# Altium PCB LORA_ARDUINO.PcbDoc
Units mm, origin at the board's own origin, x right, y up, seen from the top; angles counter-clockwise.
Board outline 68.58 x 53.34 mm, 2 copper layers (Top Layer, Bottom Layer); 51 components, 44 nets, 217 pads, 39 vias.
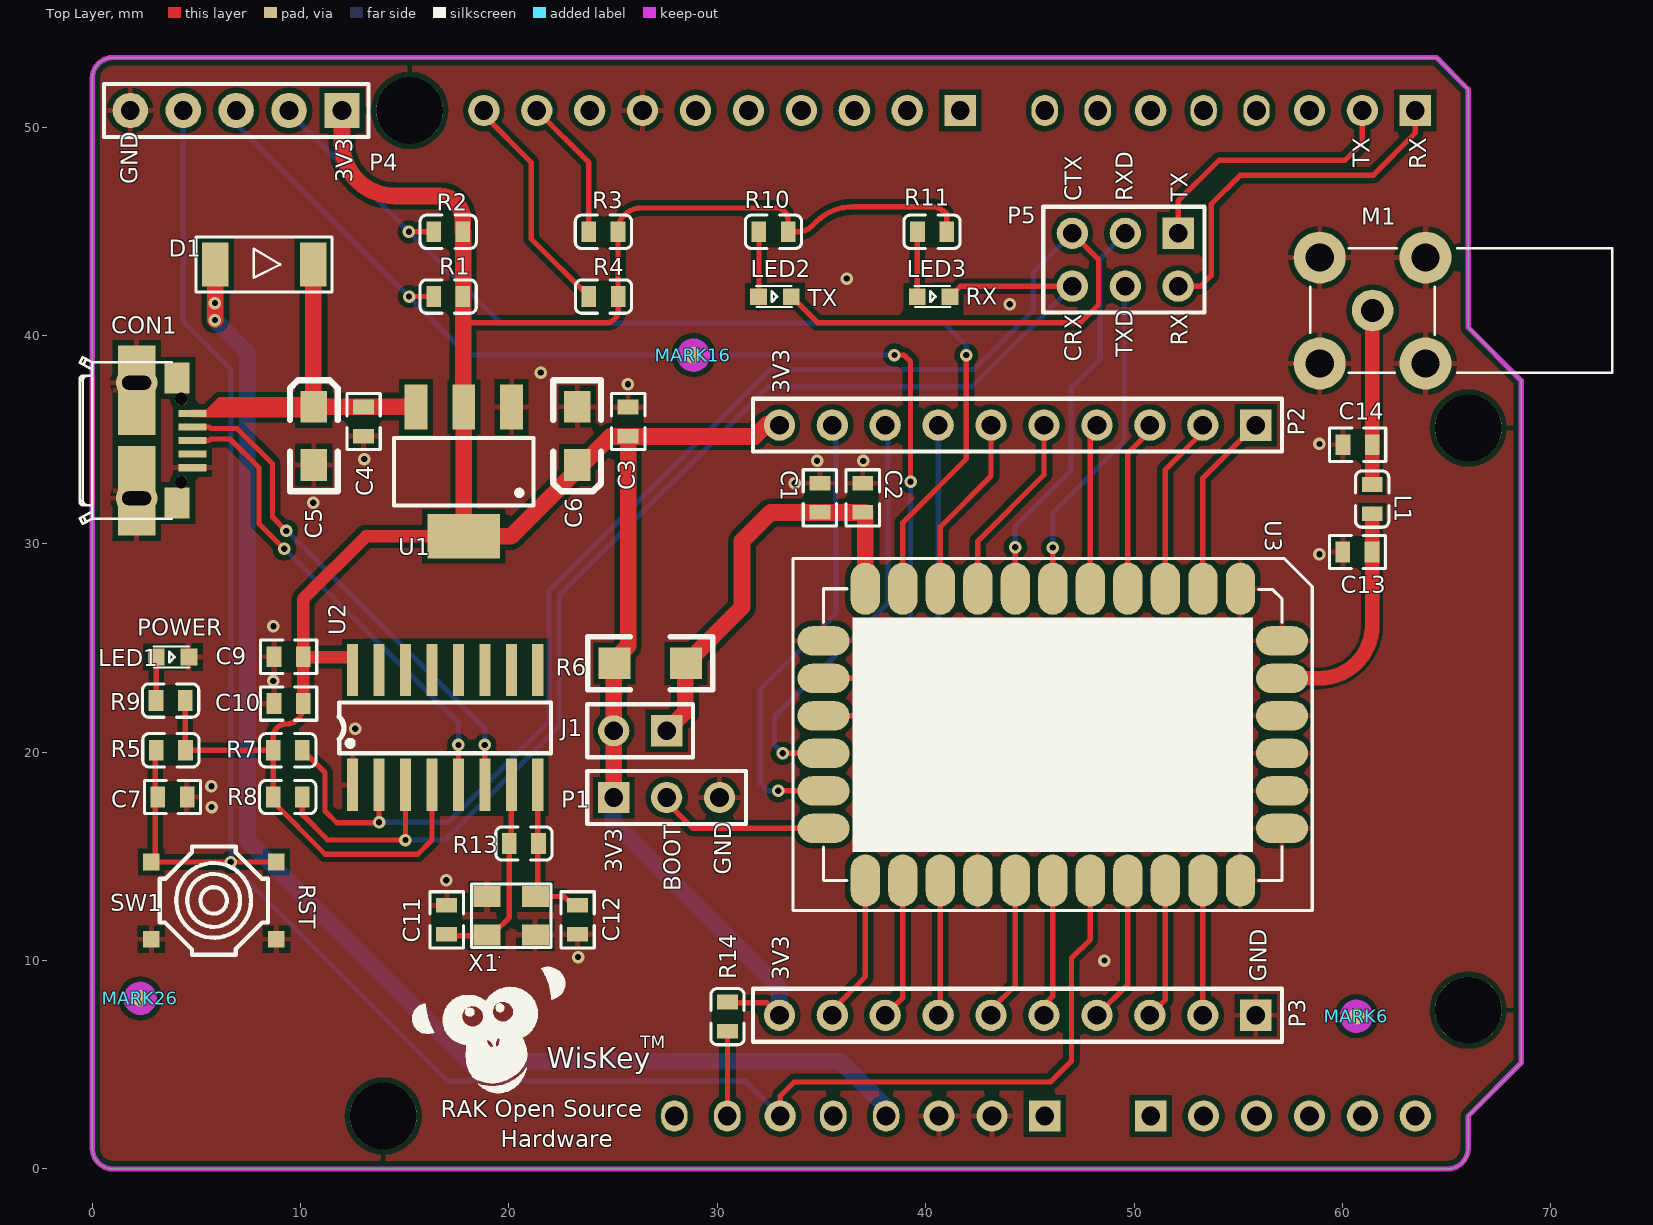
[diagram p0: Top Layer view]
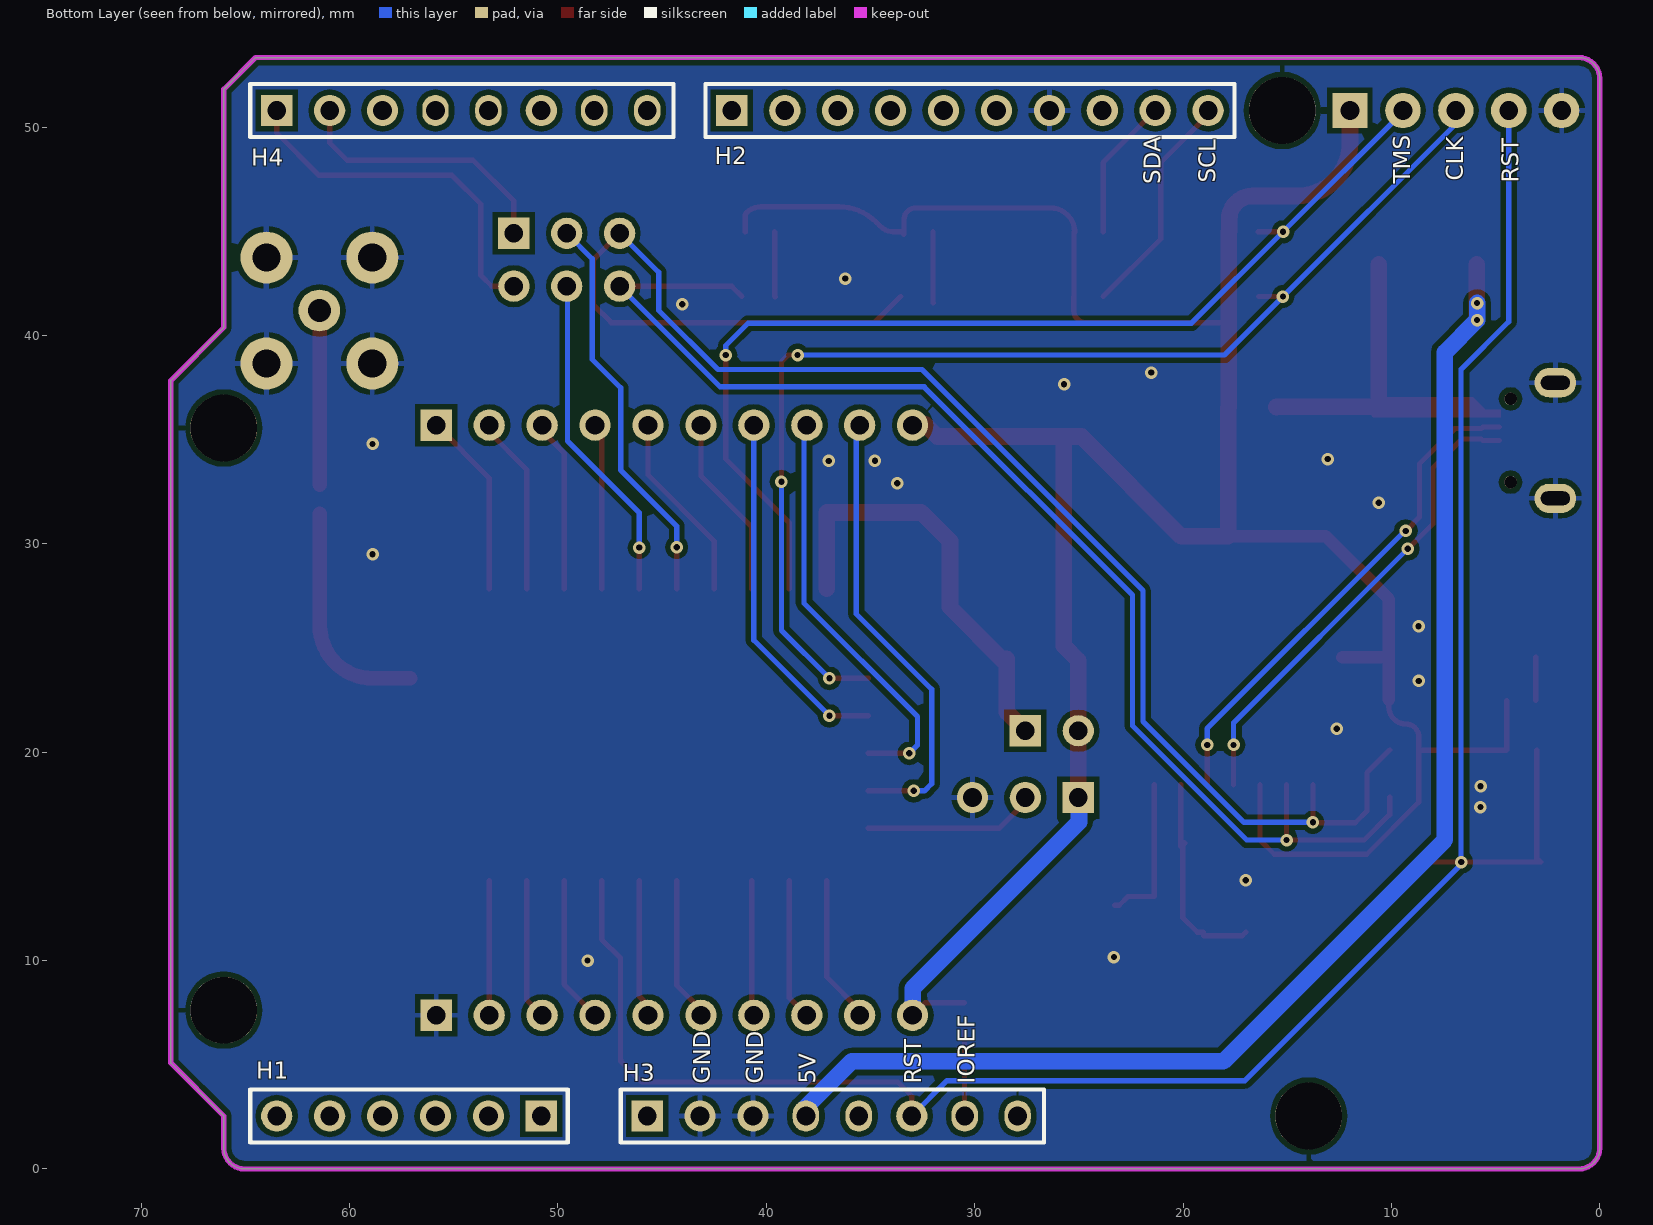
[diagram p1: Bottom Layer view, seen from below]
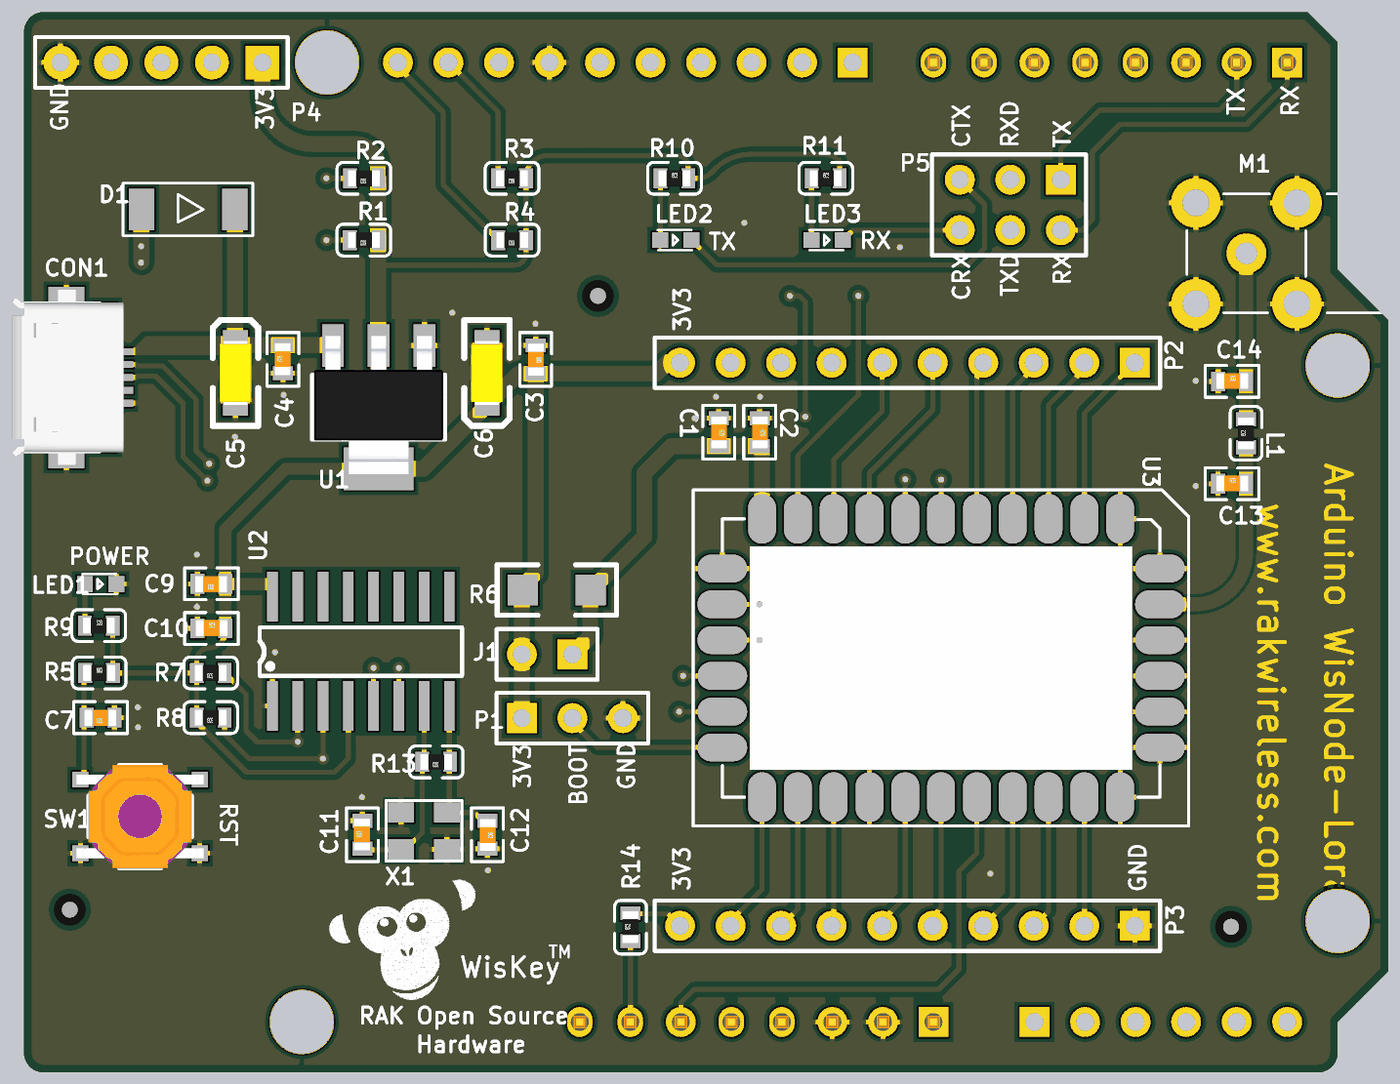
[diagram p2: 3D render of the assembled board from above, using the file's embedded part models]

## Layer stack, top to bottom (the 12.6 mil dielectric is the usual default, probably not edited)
Top Layer: signal copper 0.0356
Dielectric: dielectric 0.32, FR-4, Dk 4.8
Bottom Layer: signal copper 0.0356

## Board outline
0,1 0,52.34 cw(c1,52.34) 1,53.34 64.516,53.34 66.04,51.816 66.04,40.386 68.58,37.846 68.58,5.08 66.04,2.54 66.04,1 cw(c65.04,1) 65.04,0 1,0 cw(c1,1)

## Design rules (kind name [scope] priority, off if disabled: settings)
Clearance Clearance_1 [All vs InNet('RF_1','RF_OUT') And OnLayer('Top Layer')] p1: gap=0.152
Clearance [All] p2: gap=0.254
MinimumSolderMaskSliver MinimumSolderMaskSliver_1 [All] p1: minsoldermaskwidth=0
MinimumSolderMaskSliver [All] p2: minsoldermaskwidth=0.254
PolygonConnect PolygonConnect_1 [IsVia] p1: connectstyle=Direct reliefconductorwidth=0.254 reliefentries=4 polygonreliefangle="90 Angle"
PolygonConnect [All] p2: connectstyle=Relief reliefconductorwidth=0.254 reliefentries=4 polygonreliefangle="90 Angle"
RoutingVias [All] p1: holewidth=0.711 width=1.27 viastyle="Through Hole" minholewidth=0.711 minwidth=1.27 maxholewidth=0.711 maxwidth=1.27
SilkToSilkClearance SilkToSilkClearance_1 [All] p1: silktosilkclearance=0
SilkToSilkClearance [All] p2: silktosilkclearance=0.254
SilkscreenOverComponentPads SilkscreenOverComponentPads_1 [All] p1: minsilkscreentomaskgap=0
SilkscreenOverComponentPads [All] p2: minsilkscreentomaskgap=0.254
SolderMaskExpansion [All] p1: expansion=0.102
Width [All] p1: maxlimit=1 minlimit=0.254 preferedwidth=0.254
25 further rules are at their usual default settings.

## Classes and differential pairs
component class LORA_ARDUINO: C1 C2 C3 C4 C5 C6 C7 C9 C10 C11 C12 C13 C14 CON1 D1 H1 H2 H3 H4 J1 L1 LED1 LED2 LED3 M1 P1 P2 P3 P4 P5 R1 R2 R3 R4 R5 R6 R7 R8 R9 R10 R11 R13 R14 SW1 U1 U2 U3 X1
net class RF: RF_1 RF_OUT

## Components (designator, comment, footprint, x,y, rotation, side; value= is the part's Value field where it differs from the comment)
C1 "Cap" 0603AC 34.923,32.208 r270 top
C2 "Cap" 0603AC 36.98,32.208 r270 top
C3 "0.1μF" 0603AC 25.722,35.871 r270 top
C4 "0.1μF" 0603AC 13.022,35.871 r90 top
C5 "22uF" 3216 10.634,35.185 r90 top
C6 "22uF" 3216 23.275,35.185 r270 top
C7 "0.1uF" 0603AC 3.851,17.851 r180 top
C9 "10uF" 0603AC 9.423,24.58 r180 top
C10 "0.1uF" 0603AC 9.423,22.337 r0 top
C11 "20pF" 0603AC 17.01,11.955 r90 top
C12 "20pF" 0603AC 23.295,11.955 r270 top
C13 "0.1μF" 0603AC 60.725,29.609 r0 top
C14 "0.1μF" 0603AC 60.73,34.758 r0 top
CON1 "MICRO USB" "Micro USB通用" 3.47,34.961 r90 top
D1 "SS24A" SMA/DO-214A 8.255,43.409 r0 top
H1 "" HDR1X6 50.8,2.54 r0 bottom locked
H2 "" HDR1X10 41.656,50.8 r180 bottom locked
H3 "" HDR1X8 45.72,2.54 r180 bottom locked
H4 "" HDR1X8 63.5,50.8 r180 bottom locked
J1 "" HDR1X2 27.569,21.031 r180 top
L1 "" 0603AR 61.431,32.149 r90 top
LED1 "" LED0603 3.068,24.567 r0 top
LED2 "" LED0603 31.981,41.868 r0 top
LED3 "" LED0603 39.59,41.868 r0 top
M1 "MCX-KWE" SMA-KWE天线底座 58.912,43.741 r180 top
MARK6 "" MARK_0.8 60.678,7.329 r90 top
MARK16 "" MARK_0.8 28.856,39.06 r90 top (schematic designator MARK6)
MARK26 "" MARK_0.8 2.305,8.185 r90 top (schematic designator MARK6)
P1 "" HDR1X3 25.029,17.823 r0 top
P2 "" HDR1X10 55.84,35.697 r180 top
P3 "" HDR1X10 55.84,7.376 r180 top
P4 "" HDR1X5 11.989,50.8 r180 top
P5 "" HDR2X3 46.787,43.764 r180 top
R1 "10K" 0603AR 17.083,41.868 r180 top
R2 "10K" 0603AR 17.086,44.979 r180 top
R3 "" 0603AR 24.535,44.979 r180 top
R4 "Res1" 0603AR 24.54,41.868 r180 top
R5 "10K/5%" 0603AR 3.777,20.094 r0 top
R6 "0R/1%" 1206 26.783,24.266 r0 top
R7 "10K" 0603AR 9.385,20.094 r180 top
R8 "10K" 0603AR 9.385,17.851 r180 top
R9 "1K/5%" 0603AR 3.762,22.481 r0 top
R10 "1K/5%" 0603AR 32.698,44.979 r0 top
R11 "1K/5%" 0603AR 40.307,44.979 r0 top
R13 "1M" 0603AR 20.718,15.619 r180 top
R14 "Res1" 0603AR 30.49,7.31 r90 top
SW1 "KEY3" YH/4脚SMD轻触开关_3D_2 5.838,12.878 r270 top
U1 "LM1117IMPX-3.3" SOT-223 17.831,33.463 r180 top
U2 "CH340G" "SOIC16 - խ" 16.94,21.189 r0 top
U3 "LORA Model" LORA 55.104,27.848 r270 top locked
X1 "12MHz" XTAL-3.2X2.5 20.108,12.153 r0 top

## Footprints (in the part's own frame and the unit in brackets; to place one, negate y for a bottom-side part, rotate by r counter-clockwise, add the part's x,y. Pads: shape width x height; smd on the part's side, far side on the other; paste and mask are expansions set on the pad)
0603AC [mm]
  rect 0.7x1 smd: 1(-0.7,0) 2(0.7,0)
  silkscreen extent -1.35,-0.8 1.35,0.8, body extent -0.79,-0.38 0.81,0.42, height 0.3
0603AR [mm]
  rect 0.7x1 smd: 1(-0.7,0) 2(0.7,0)
  silkscreen extent -1.35,-0.8 1.35,0.8, body extent -0.8,-0.4 0.8,0.4, height 0.3
1206 [mil]
  rect 60x60 smd: 1(-67.5,0) 2(67.5,0)
  silkscreen extent -118,-50 118,50
3216 [mil]
  rect 60x50 smd: 1(55,0) 2(-55,0)
  silkscreen extent -105,-45 105,45, body extent -63,-31 63,31, height 63
HDR1X2 [mm] "Connector; Header; 2 Posit"
  rect 1.5x1.5 hole 0.9: 1(0,0)
  round 1.5 hole 0.9: 2(2.54,0)
  silkscreen extent -1.27,-1.27 3.81,1.27
HDR1X3 [mm] "Connector; Header; 3 Posit"
  rect 1.5x1.5 hole 0.9: 1(0,0)
  round 1.5 hole 0.9: 2(2.54,0) 3(5.08,0)
  silkscreen extent -1.27,-1.27 6.35,1.27
HDR1X5 [mm] "Connector; Header; 5 Position"
  rect 1.7x1.7 hole 0.9: 1(0,0)
  round 1.7 hole 0.9: 2(2.54,0) 3(5.08,0) 4(7.62,0) 5(10.16,0)
  silkscreen extent -1.27,-1.27 11.43,1.27
HDR1X6 [mm]
  rect 1.5x1.5 hole 0.9: 1(0,0)
  round 1.5 hole 0.9: 2(2.54,0) 3(5.08,0) 4(7.62,0) 5(10.16,0) 6(12.7,0)
  silkscreen extent -1.27,-1.27 13.97,1.27
HDR1X8 [mm] "Connector; Header; 8 Position"
  rect 1.5x1.5 hole 0.9: 1(0,0)
  round 1.5 hole 0.9: 2(2.54,0) 3(5.08,0) 6(12.7,0)
  oval 1.27x1.5 hole 0.9: 4(7.62,0) 5(10.16,0) 7(15.24,0) 8(17.78,0)
  silkscreen extent -1.27,-1.27 19.05,1.27, body extent -1.27,-1.27 19.05,1.27, height 0.7
HDR1X10 [mm] "Connector; Header; 10 Posit"
  rect 1.5x1.5 hole 0.9: 1(0,0)
  round 1.5 hole 0.9: 2(2.54,0) 3(5.08,0) 4(7.62,0) 5(10.16,0) 6(12.7,0) 7(15.24,0) 8(17.78,0) 9(20.32,0) 10(22.86,0)
  silkscreen extent -1.27,-1.27 24.13,1.27
HDR2X3 [mm]
  rect 1.5x1.5 hole 0.9: 1(-5.334,-1.143)
  round 1.5 hole 0.9: 2(-5.334,1.397) 3(-2.794,-1.143) 4(-2.794,1.397) 5(-0.254,-1.143) 6(-0.254,1.397)
  silkscreen extent -6.6,-2.41 1.14,2.67
LED0603 [mm]
  rect 0.8x0.8 smd: 1(0,0) 2(1.575,0)
  silkscreen extent -0.13,-0.51 1.6,0.51, body extent -0.06,-0.47 1.64,0.48, height 0.9
LORA [mm]
  oval 2.5x1.4 smd: 1(0,0) 2(0,-1.8) 3(0,-3.6) 4(0,-5.4) 5(0,-7.2) 6(0,-9) 7(0,-10.8) 8(0,-12.6) 9(0,-14.4) 10(0,-16.2) 11(0,-18) 18(14,-18) 19(14,-16.2) 20(14,-14.4) 21(14,-12.6) 22(14,-10.8) 23(14,-9) 24(14,-7.2) 25(14,-5.4) 26(14,-3.6) 27(14,-1.8) 28(14,0)
  oval 1.4x2.5 smd: 12(2.5,-20) 13(4.3,-20) 14(6.1,-20) 15(7.9,-20) 16(9.7,-20) 17(11.5,-20) 29(11.5,2) 30(9.7,2) 31(7.9,2) 32(6.1,2) 33(4.3,2) 34(2.5,2)
  silkscreen extent -1.45,-21.46 15.45,3.45
MARK_0.8 [mm]
  round 0.8 smd: 1(0,0)
  Top Layer keep-out circle w0.4: c0,0 r0.6
"Micro USB通用" [mm]
  rect 0.35x1.349 smd: 1(1.3,-1.34) 2(0.65,-1.34) 3(0,-1.34) 4(-0.65,-1.34) 5(-1.3,-1.34)
  rect 4.3x1.8 smd: 6(2.413,1.34) 7(-2.413,1.34)
  oval 1.4x2 hole 0.66 slot 1.4 at 90 deg: 6(2.775,1.34) 7(-2.775,1.34)
  rect 1.5x1.2 smd: 8(3,-0.61) 9(-3,-0.61)
  round 0.6 hole 0.6 unplated paste+0: ""(-2,-0.81) ""(2,-0.81)
  silkscreen extent -4.03,-0.35 4.03,4.08, body extent -4.4,-1.53 4.4,4.07, height 2.74
SMA-KWE天线底座 [mm]
  round 2 hole 1.1: 1(-2.54,2.54)
  round 2.5 hole 1.35: 2(-5.08,5.08) 3(-5.08,0) 4(0,0) 5(0,5.08)
  silkscreen extent -14.05,-0.45 0.45,5.53
SMA/DO-214A [mm]
  rect 1.27x2.1 smd: 1(-2.349,0) 2(2.349,0)
  silkscreen extent -3.28,-1.32 3.25,1.32
"SOIC16 - խ" [mm]
  rect 0.533x2.5 smd: 1(-4.445,-2.75) 2(-3.175,-2.75) 3(-1.905,-2.75) 4(-0.635,-2.75) 5(0.635,-2.75) 6(1.905,-2.75) 7(3.175,-2.75) 8(4.445,-2.75) 9(4.445,2.75) 10(3.175,2.75) 11(1.905,2.75) 12(0.635,2.75) 13(-0.635,2.75) 14(-1.905,2.75) 15(-3.175,2.75) 16(-4.445,2.75)
  silkscreen extent -5.08,-1.24 5.08,1.2
SOT-223 [mm] "SOT-223/SC-73; 4 Leads; Body 6.7 x 7.3 mm, inc. leads (LxW max)"
  rect 1.1x2.15 smd: 1(2.3,-3.1) 2(0,-3.1) 3(-2.3,-3.1)
  rect 3.5x2.15 smd: 2(0,3.1)
  silkscreen extent -3.35,-1.63 3.35,1.63, body extent -3.25,-3.58 3.25,3.38, height 1.65
XTAL-3.2X2.5 [mil] "XTAL-3.2X2.5"
  rect 51x40 smd: 1(-45.5,-36.5) 2(45.5,-36.5) 3(45.5,36.5) 4(-45.5,36.5)
  silkscreen extent -75,-60 75,60
YH/4脚SMD轻触开关_3D_2 [mm] "4脚 按键 4X4X1.5贴片铜头防水"
  rect 0.8x0.8 smd: 1(1.85,3) 2(1.85,-3) 3(-1.85,3) 4(-1.85,-3)
  silkscreen extent -2.6,-2.6 2.6,2.6, body extent -2.6,-3.2 2.6,3.2, height 1.5

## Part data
C1 C2: "Capacitor"
C3: library part Cap, "Capacitor"
C4 C9 C10 C13 C14: library part CAP, "Capacitor"
C5 C6: library part CAP
C7: library part C
C11 C12: library part "CAP NP_Dup1"
D1: library part DIODE
H1: library part "Header 6", "Header, 6-Pin"
H2 P2 P3: library part "Header 10", "Header, 10-Pin"
H3 H4: library part "Header 8", "Header, 8-Pin"
J1: library part "Header 2", "Header, 2-Pin"
L1 R5 R7 R8: library part RES
LED1 LED2 LED3: library part LED
MARK6 MARK16 MARK26: library part MARK点
P1: library part "Header 3", "Header, 3-Pin"
P4: library part "Header 5", "Header, 5-Pin"
P5: library part "Header 3X2", "Header, 3-Pin, Dual row"
R1 R2: library part R_5
R3: library part Res1, "Resistor"
R4 R14: "Resistor"
R6 R9 R10 R11: library part Res2, "Resistor"
R13: library part R_0
SW1: library part KEY1
U1: "Voltage Regulator"
U2: "USB to TTL Serial / UART"
X1: library part Crystal_SMD_2

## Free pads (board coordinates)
  round 3.2 hole 3.2: 1(13.97,2.54) 1(15.24,50.8) 1(66.04,7.62) 1(66.04,35.56)

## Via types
v1: diameter 0.6, hole 0.3, Top Layer to Bottom Layer, tented both sides, 39 vias

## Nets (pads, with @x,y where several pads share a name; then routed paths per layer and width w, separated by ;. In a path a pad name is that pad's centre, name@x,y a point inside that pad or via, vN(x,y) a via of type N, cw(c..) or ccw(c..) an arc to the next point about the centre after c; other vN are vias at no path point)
A_RX: H4.1 P5.2 | length 17.5
  Top Layer w0.254: P5.2 53.181,42.367 53.703,42.889 53.703,46.301 55.089,47.686 61.468,47.686 63.5,49.719 H4.1
A_TX: H4.2 P5.1 | length 13.1
  Top Layer w0.254: P5.1 52.121,46.453 54.078,48.41 60.118,48.41 60.96,49.252 H4.2
BOOT0: P1.2 U3.17 | length 8.2
  Top Layer w0.254: P1.2@27.691,17.823 27.691,17.494 28.837,16.348 U3.17
CH_RX: LED3.2 P5.6 R8.1 U2.3 | length 61.7
  Top Layer w0.254: R8.1 10.085,17.006 11.305,15.786 v1(15.035,15.786) U2.3 ; LED3.2 41.664,42.367 P5.6
  Bottom Layer w0.254: v1(15.035,15.786) 16.944,15.786 22.43,21.272 22.43,27.542 32.426,37.538 42.211,37.538 P5.6
CH_TX: LED2.2 P5.5 R7.1 U2.2 | length 77.3
  Top Layer w0.254: R7.1@10.085,20.107 11.17,19.022 11.17,17.181 11.734,16.617 13.765,16.617 v1(13.765,16.635) U2.2 ; LED2.2 34.806,40.619 47.438,40.619 48.292,41.473 48.292,43.656 P5.5
  Bottom Layer w0.254: v1(13.765,16.635) 17.075,16.635 21.922,21.482 21.922,27.756 32.531,38.365 42.32,38.365 45.168,41.213 45.168,43.035 P5.5
CHRG: P2.1 U3.2 | length 8.9
  Top Layer w0.254: U3.2 53.304,33.16 P2.1
GND: C1.1 C2.1 C3.1 C4.1 C5.2 C6.2 C7.1 C9.2 C10.1 C11.2 C12.2 C13.1 C14.1 CON1.5 CON1.6 CON1.7 H2.7 H3.2 H3.3 LED1.2 M1.2 M1.3 M1.4 M1.5 P1.3 P3.1 P4.5 SW1.1 SW1.2 U1.3 U2.1 U3.1 U3.12 U3.21 U3.28 U3.29 U3.30 U3.31 U3.32 U3.34 X1.2 X1.4
  other v1: 48.578,10.004 23.316,10.168 16.99,13.85 5.729,17.367 5.724,18.365 12.622,21.132 8.694,23.423 8.695,26.049 58.901,29.5 10.612,31.974 33.712,32.909 34.79,33.986 37.002,33.979 13.053,34.073 58.901,34.794 25.713,37.655 21.526,38.22 44.039,41.504 36.209,42.736
INT_ACC1: P2.3 U3.4 | length 8.3
  Top Layer w0.254: U3.4 49.704,34.362 50.76,35.419 P2.3
INT_ACC2: P2.2 U3.3 | length 8.6
  Top Layer w0.254: U3.3 51.504,33.574 53.3,35.371 P2.2
LVCC_3V3: C1.2 C2.2 J1.1 R6.2 U3.11 | length 21
  Top Layer w0.8: J1.1 28.461,21.923 R6.2@28.461,24.477 ; R6.2 31.189,26.958 31.189,30.138 32.56,31.508 C2.2@37.107,31.508 ; C2.2 37.104,31.385 U3.11 U3.11@37.107,27.851
NetD1_1: D1.1 H3.4 | length 65.5
  Top Layer w0.8: v1@5.905,40.761 D1.1
  Bottom Layer w0.8: v1(5.886,41.561) v1(5.886,40.742) 7.437,39.192 7.437,15.792 18.064,5.164 35.905,5.164 38.1,2.97 H3.4
NetH2_9: H2.9 R3.2 | length 6.9
  Top Layer w0.254: H2.9 23.835,48.301 R3.2
NetH2_10: H2.10 R4.2 | length 11
  Top Layer w0.254: H2.10 18.796,50.58 21.072,48.305 21.072,44.636 R4.2
NetH3_7: H3.7 R14.1 | length 4.1
  Top Layer w0.254: H3.7 30.49,2.54 R14.1
NetLED1_1: LED1.1 R9.1 | length 2.1
  Top Layer w0.254: R9.1 ccw(c3.062,22.487) 3.068,22.487 LED1.1
NetLED2_1: LED2.1 R10.1 | length 3.4
  Top Layer w0.254: LED2.1@31.981,41.562 31.998,41.579 R10.1
NetLED3_1: LED3.1 R11.1 | length 3.2
  Top Layer w0.254: LED3.1@39.58,41.857 LED3.1 R11.1@39.59,44.939 ; R11.1@39.59,44.939 cw(c39.647,44.939) R11.1 ccw(c39.647,44.939) R11.1@39.59,44.939
PA15: P2.7 U3.14 | length 17.3
  Top Layer w0.254: U3.14 v1(36.974,21.748)
  Bottom Layer w0.254: v1(36.974,21.748) 40.6,25.374 P2.7
PB10: P3.4 U3.25 | length 7.1
  Top Layer w0.254: P3.4 49.704,8.859 U3.25
RF_1: C14.2 L1.2 M1.1 | length 8.4
  Top Layer w0.709: M1.1@61.423,41.172 cw(c61.452,41.172) M1.1 ccw(c61.452,41.179) 61.431,41.179 L1.2
RF_OUT: C13.2 L1.1 U3.33 | length 11.1
  Top Layer w0.709: U3.33 58.891,23.548 ccw(c58.891,26.088) 61.431,26.088 L1.1
RST: C7.2 H3.6 P4.4 R5.1 SW1.3 SW1.4 U3.24 | length 105
  Top Layer w0.254: R5.1@3.021,20.094 3.021,14.911 SW1.4 SW1.3 ; P4.4@4.369,50.416 P4.4 ; H3.6 33.02,3.5 33.696,4.176 45.984,4.176 46.993,5.184 ; 46.993,5.215 47.004,5.226 47.004,10.121 47.904,11.02 U3.24
  Bottom Layer w0.254: P4.4 4.369,40.665 6.656,38.378 v1@6.656,14.728 ; v1@6.667,14.728 6.667,14.604 17.036,4.235 31.325,4.235 H3.6
  other v1: 6.651,14.728
SCL: P3.3 U3.26 | length 6.8
  Top Layer w0.254: P3.3 51.504,8.119 U3.26
SCL1: P3.9 U3.18 | length 7.1
  Top Layer w0.254: P3.9 35.52,7.624 37.104,9.207 U3.18
SDA: P3.2 U3.27 | length 6.5
  Top Layer w0.254: P3.2 53.304,7.379 U3.27
SDA1: P3.8 U3.19 | length 6.8
  Top Layer w0.254: P3.8 38.904,8.219 U3.19
SW_PB_SPST1: P2.8 U3.15 | length 20
  Top Layer w0.254: v1(33.138,19.948) U3.15
  Bottom Layer w0.254: v1(33.138,19.948) 32.747,20.339 32.747,21.706 38.189,27.148 P2.8@38.189,35.568
SW_PB_SPST2: P2.9 U3.16 | length 21.7
  Top Layer w0.254: v1(32.929,18.148) U3.16
  Bottom Layer w0.254: v1(32.929,18.148) 32.406,18.148 32.067,18.487 32.067,23.025 35.691,26.648 P2.9@35.691,35.526
SWD_CLK: P4.3 R1.2 U3.13 | length 57.1
  Top Layer w0.254: 15.521,41.868 R1.2 ; U3.13 v1(36.974,23.548) ; v1(38.505,39.06) 38.963,39.06 39.278,38.745 v1(39.278,32.987)
  Bottom Layer w0.254: P4.3@6.909,50.296 P4.3 6.909,50.167 v1(15.207,41.868) 18.015,39.06 v1(38.505,39.06) ; v1(36.974,23.548) 39.278,25.852 v1(39.278,32.987)
SWD_TMS: P4.2 R2.2 U3.10 | length 51.7
  Top Layer w0.254: v1(15.198,44.979) R2.2 ; U3.10 38.904,31.027 41.946,34.07 v1(41.946,39.063)
  Bottom Layer w0.254: P4.2@9.449,50.374 P4.2@9.449,50.728 ; P4.2 P4.2@9.449,50.728 ; v1(15.198,44.979) P4.2@9.449,50.728 ; v1@15.212,44.979 19.596,40.595 40.869,40.595 41.946,39.518 v1(41.946,39.063)
SYNC: P2.4 U3.5 | length 8
  Top Layer w0.254: U3.5 47.904,35.38 P2.4
UART1_CTS: P2.6 U3.9 | length 8.9
  Top Layer w0.254: U3.9 40.704,30.823 43.14,33.26 P2.6
UART1_RTS: P2.5 U3.8 | length 9.2
  Top Layer w0.254: U3.8 42.504,30.142 45.68,33.318 P2.5
UART1_RX: P5.3 U3.7 | length 19.2
  Top Layer w0.254: U3.7 v1(44.304,29.836)
  Bottom Layer w0.254: v1(44.304,29.836) 44.304,30.858 46.995,33.549 46.995,37.492 48.354,38.852 48.354,43.681 P5.3
UART1_TX: P5.4 U3.6 | length 15.9
  Top Layer w0.254: U3.6 v1(46.104,29.821)
  Bottom Layer w0.254: v1(46.104,29.821) 46.104,31.497 49.547,34.941 P5.4@49.547,42.367
UART4_RX: P3.6 U3.22 | length 7
  Top Layer w0.254: P3.6 43.14,7.651 44.304,8.815 U3.22
UART4_TX: P3.5 U3.23 | length 6.6
  Top Layer w0.254: P3.5 45.68,7.867 46.104,8.291 U3.23
USB_DM: CON1.2 U2.6 | length 24.2
  Top Layer w0.254: CON1.2 5.611,35.611 5.682,35.54 6.955,35.54 8.647,33.848 8.647,31.284 v1(9.309,30.623) ; U2.6 v1(18.845,20.35)
  Bottom Layer w0.254: v1@9.333,30.648 18.845,21.137 v1(18.845,20.35)
USB_DP: CON1.3 U2.5 | length 22.6
  Top Layer w0.254: CON1.3 5.611,34.961 ; 5.682,35.032 6.621,35.032 8.001,33.651 8.001,30.966 v1@9.047,29.92 ; U2.5 v1(17.575,20.348)
  Bottom Layer w0.254: v1(9.218,29.767) 17.575,21.411 v1(17.575,20.348)
VBAT_ANA: P3.7 U3.20 | length 6.5
  Top Layer w0.254: P3.7 40.704,7.479 U3.20
VCC5V: C4.2 C5.1 CON1.1 D1.2 U1.1 | length 11.5
  Top Layer w0.8: D1.2 10.61,43.403 C5.1@10.61,36.785 ; C5.1 15.512,36.582 U1.1
VCC_3V3: C3.2 C6.1 C9.1 C10.2 J1.2 P1.1 P2.10 P3.10 P4.1 R1.1 R2.1 R3.1 R4.1 R5.2 R6.1 R7.2 R8.2 R9.2 R10.2 R11.2 R14.2 U1.2 U2.4 U2.16 | length 147.7
  Top Layer w0.254: R9.2 4.462,20.109 R5.2 R7.2 ; C10.2@10.123,22.512 10.123,22.178 cw(c9.296,22.178) 9.296,21.351 ccw(c9.296,20.74) 8.685,20.74 R7.2 ; P4.1@11.419,50.23 P4.1 ; U2.4 16.305,15.788 15.621,15.105 11.183,15.105 8.685,17.602 R8.2 R7.2 ; 17.807,40.645 ccw(c17.843,40.645) 17.843,40.609 24.656,40.609 ccw(c24.656,41.192) 25.24,41.192 R4.1 25.235,41.873 R3.1 ; R3.1@25.182,45.048 25.182,44.987 ccw(c25.202,44.987) 25.202,44.967 cw(c26.36,44.967) 26.36,46.125 32.82,46.125 cw(c32.82,45.556) 33.389,45.556 33.389,44.865 ccw(c33.389,44.874) 33.398,44.874 R10.2 ; R14.2@30.49,7.977 32.379,7.977 P3.10 ; R10.2@33.443,44.869 cw(c33.552,44.979) R10.2 ; R11.2@41.007,44.967 cw(c41.004,44.965) R11.2@41.008,44.965 ; R11.2 41.007,45.781 ccw(c40.859,45.781) 40.964,45.886 ccw(c40.242,45.164) 40.242,46.185 36.523,46.185 ccw(c36.523,43.645) 34.727,45.441 34.518,45.232 cw(c33.906,45.844) 33.906,44.979 R10.2
  Top Layer w0.6: C10.2@10.123,22.512 C9.1 10.123,27.346 13.141,30.363 U1.2@17.831,30.363 ; C9.1@10.212,24.561 U2.16@12.351,24.561
  Top Layer w0.8: P4.1 11.989,49.238 ccw(c14.529,49.238) 14.529,46.698 16.671,46.698 cw(c16.671,45.583) 17.786,45.583 R2.1 ; U1.2@17.807,36.563 R2.1@17.807,44.979 ; U1.2@17.831,36.563 17.831,30.363 20.089,30.363 24.875,35.15 31.797,35.15 32.388,35.741 P2.10@32.98,35.741 ; P1.1 25.029,20.889 25.029,24.407 25.722,25.1 C3.2@25.722,35.059 ; J1.2@25.032,21.239 J1.2@25.045,21.226
  Bottom Layer w0.8: P1.1@25.16,17.993 24.994,17.826 24.994,16.654 32.98,8.667 P3.10
XIN: C11.1 R13.2 U2.7 X1.1 | length 10.2
  Top Layer w0.254: C11.1@16.997,11.358 17.158,11.198 X1.1@19,11.198 ; X1.1@19.016,11.36 19.315,11.36 20.018,12.062 R13.2 ; R13.2@19.991,15.692 19.926,15.627 R13.2@20.092,15.46 ; R13.2@20.115,15.513 U2.7
XOUT: C12.1 R13.1 U2.8 X1.3 | length 7.4
  Top Layer w0.254: U2.8 21.385,13.08 22.637,13.08 23.062,12.655 C12.1
pads on no net: CON1. CON1.4 CON1.8 CON1.9 H1.1 H1.2 H1.3 H1.4 H1.5 H1.6 H2.1 H2.2 H2.3 H2.4 H2.5 H2.6 H2.8 H3.1 H3.5 H3.8 H4.3 H4.4 H4.5 H4.6 H4.7 H4.8 MARK6.1 MARK16.1 MARK26.1 U2.9 U2.10 U2.11 U2.12 U2.13 U2.14 U2.15

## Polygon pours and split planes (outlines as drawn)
GND on Top Layer "Top Layer-No Net" (solid, remove dead copper, pour order 1000): -0.227,53.494 -0.227,-0.493 -0.024,-0.696 69.161,-0.696 68.857,-0.392 68.857,53.7
GND on Bottom Layer "Top Layer-No Net" (solid, remove dead copper, pour order 1001): -0.17,53.549 -0.17,-0.416 -0.097,-0.49 -0.023,-0.564 69.52,-0.564 69.52,53.402 69.667,53.549

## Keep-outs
Keep-Out Layer:
  the board outline again, w0.254

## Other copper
Top Layer:
  region net VCC5V: 4.748,36.435 4.748,36.086 10.895,36.086 10.935,36.126 10.935,37.029 6.075,37.029 5.481,36.435

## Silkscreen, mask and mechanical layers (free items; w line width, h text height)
Top Overlay:
  drawing of 2317 lines, arcs and shapes, not listed
  text "TX" at 61.307,48.075 h0.8 r90
  text "RX" at 64.028,47.991 h0.8 r90
  text "3V3" at 12.504,47.335 h0.8 r90
  text "GND" at 2.176,47.251 h0.8 r90
  text "CTX" at 47.503,46.432 h0.8 r90
  text "RXD" at 49.936,46.432 h0.8 r90
  text "TX" at 52.569,46.427 h0.8 r90
  text "RX" at 41.928,41.472 h0.8
  text "TX" at 34.338,41.414 h0.8
  text "RX" at 52.569,39.516 h0.8 r90
  text "TXD" at 49.936,38.955 h0.8 r90
  text "CRX" at 47.503,38.739 h0.8 r90
  text "3V3" at 33.47,37.196 h0.8 r90
  text "POWER" at 2.165,25.581 h0.8
  text "3V3" at 25.442,14.214 h0.8 r90
  text "GND" at 30.67,14.13 h0.8 r90
  text "RST" at 9.902,13.667 h0.8 r270
  text "BOOT" at 28.241,13.334 h0.8 r90
  text "3V3" at 33.454,9.059 h0.8 r90
  text "GND" at 56.372,8.995 h0.8 r90
  text "TM" at 26.307,5.782 h0.6
  text "WisKey" at 21.814,4.821 h1
  text "RAK Open Source" at 16.736,2.48 h0.8
  text "Hardware" at 19.614,1.035 h0.8
Bottom Overlay:
  text "CLK" at 6.562,47.419 h0.8 r270
  text "RST" at 3.893,47.335 h0.8 r270
  text "SCL" at 18.421,47.327 h0.8 r270
  text "TMS" at 9.084,47.293 h0.8 r270
  text "SDA" at 21.072,47.259 h0.8 r270
  text "IOREF" at 29.996,4.078 h0.8 r270
  text "RST" at 32.559,4.078 h0.8 r270
  text "5V" at 37.64,4.078 h0.8 r270
  text "GND" at 40.159,4.078 h0.8 r270
  text "GND" at 42.688,4.078 h0.8 r270
Top Solder:
  text "Arduino WisNode-Lora" at 65.445,30.784 h1.3 r270
  text "www.rakwireless.com" at 63.117,29.236 h1.3 r270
